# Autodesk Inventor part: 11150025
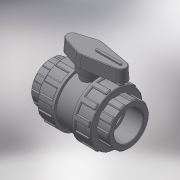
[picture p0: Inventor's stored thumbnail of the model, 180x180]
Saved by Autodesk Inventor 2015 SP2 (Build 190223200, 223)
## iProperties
Created: 2017-11
Part Number: 11150025
Material: Generic
Description: PLASSON 2/NUT VALVE CEM. PVC 25
Document SubType Name: Modeling
Designer: KIM
Density: 1 g/cm^3
Appearance: Default
Author: KIM
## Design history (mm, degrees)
derived "111500.ipt"
feature "Solid1::111500.ipt"
tag "TaggingFeature1"
body "Solid1"
other parameters: "d0" = 89, "d1" = 25, "d2" = 55, "d3" = 19, "d5" = 13.3, "d7" = 35, "d8" = 49.5, "d13" = 0.75, "d23" = 19, "d24" = 52.8, "d25" = 0.5, "d26" = 0.75, "d27" = 8.25, "d28" = 4.125, "d29" = 14.25, "d30" = 0, "d35" = 0.75, "d39" = 27.5, "d45" = 360 deg, "d47" = 0.5, "d50" = 30.25, "d51" = 16.5, "d53" = 0, "d55" = 5, "d56" = 2.5, "d57" = 13.3, "d58" = 0, "d59" = 0.75, "d61" = 360 deg, "d63" = 22, "d64" = 54, "d66" = 73, "d68" = 11, "d69" = 21.9, "d70" = 13.5, "d71" = 3 deg, "d73" = 1.1, "d74" = 29.2, "d75" = 1.62, "d76" = 0, "d77" = 0.5, "d_" = 25, "l_" = 19, "H_" = 89, "K_" = 55, "F_" = 54, "J_" = 73, "d67" = 22, "d72" = 5.5
